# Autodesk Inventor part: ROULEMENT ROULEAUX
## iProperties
Created: 2004-11
Part Number: ROULEMENT ROULEAUX
Document SubType Name: Modeling
Designer: Bruno
Manufacturer: Standard
Standards Organization: Custom
Author: Bruno
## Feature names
1. Base1
